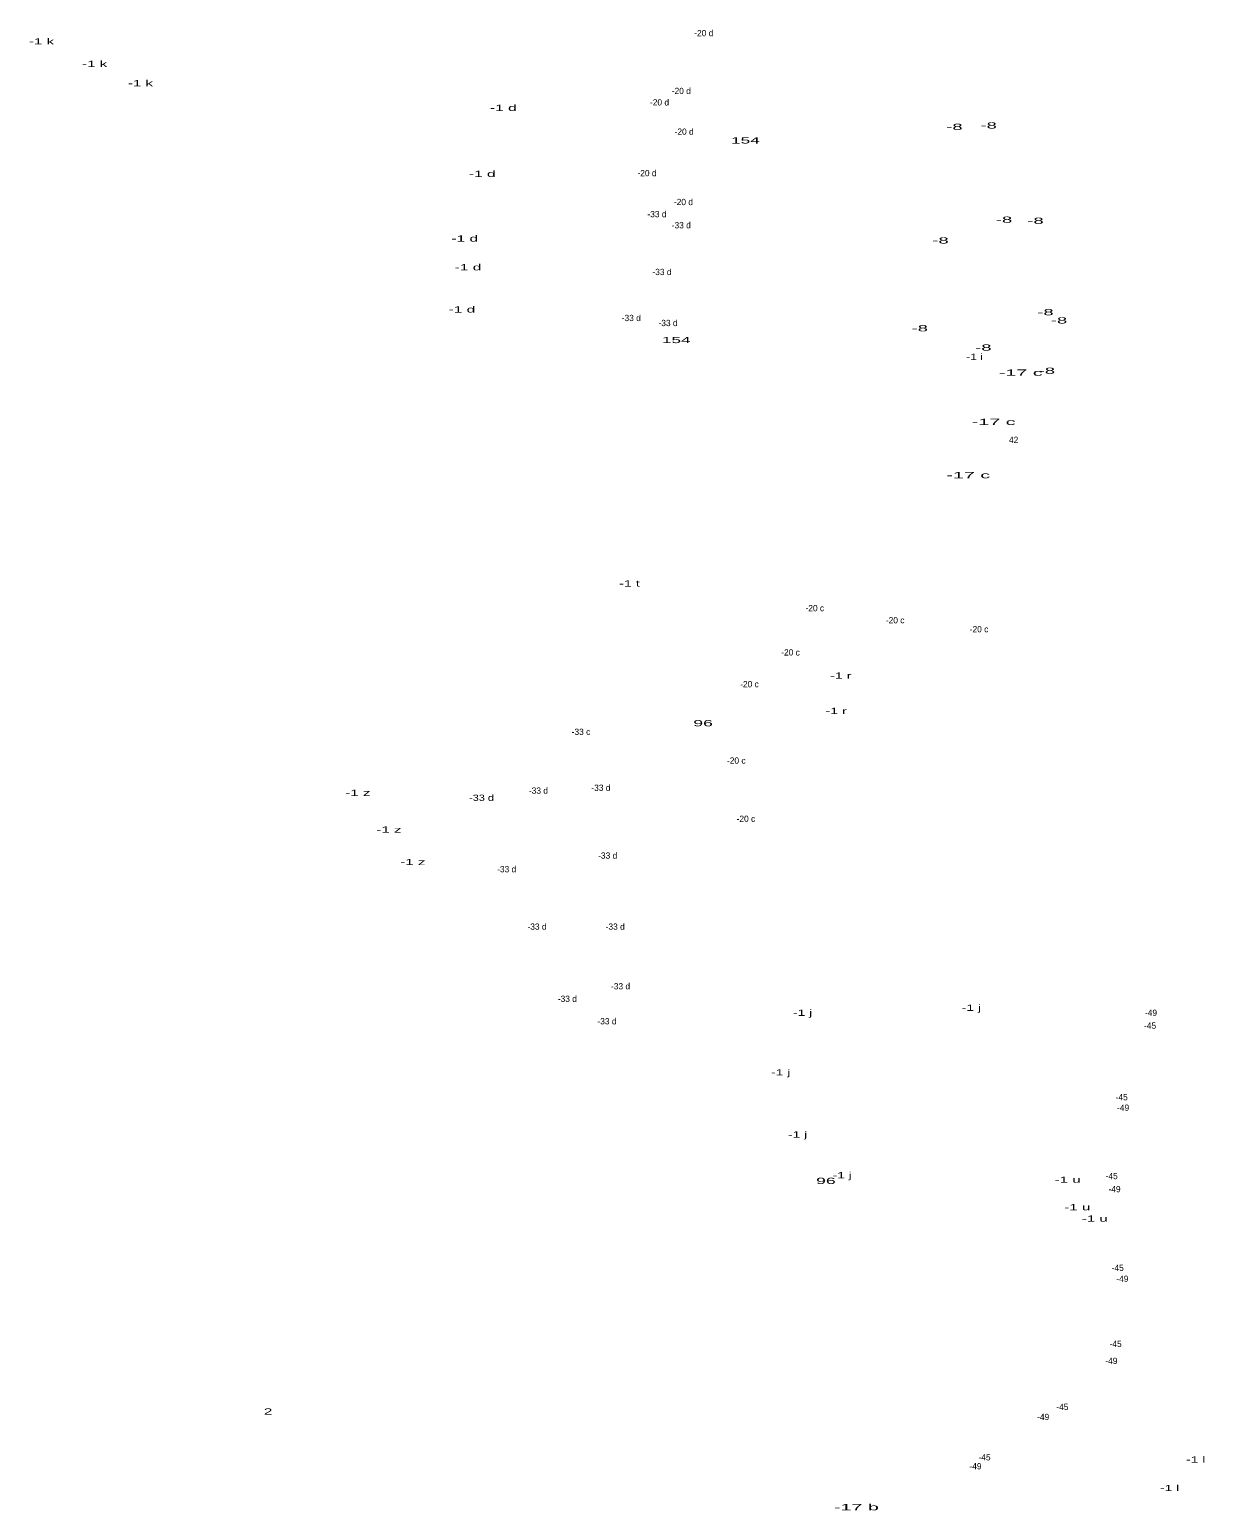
# Model space of a CAD drawing. Extents: x -668622 to -666786, y -990362 to -986505.
# Drawn here: x -667536 to -666786, y -988432 to -987486 of the extents above; entities that cross this region are included whole.
import ezdxf
from ezdxf.enums import TextEntityAlignment as Align

# ---------------------------------------------------------------- set-up
doc = ezdxf.new("R2010")
doc.units = 0
doc.header["$LTSCALE"] = 1.6
doc.layers.add('24', color=7, linetype='Continuous')

msp = doc.modelspace()

# ---------------------------------------------------------------- texts
at = {"layer": '24'}
for s, width, p in [('-1 k', 1.8, (-667528.436, -987495.94)), ('-1 k', 1.8, (-667494.466, -987510.31)), ('-1 k', 1.8, (-667465.286, -987522.62)), ('-1 d', 1.85, (-667233.561, -987538.35)), ('-8', 2.2, (-666945.534, -987550.53)), ('-8', 2.2, (-666923.654, -987549.62)), ('154', 2.05, (-667079.023, -987559.18)), ('-1 d', 1.85, (-667247.011, -987580.53)), ('-8', 2.2, (-666913.854, -987609.82)), ('-8', 2.2, (-666893.784, -987610.5)), ('-1 d', 1.85, (-667258.181, -987621.81)), ('-8', 2.2, (-666954.424, -987623.05)), ('-1 d', 1.85, (-667256.131, -987640.19)), ('-1 d', 1.85, (-667260.011, -987667.1)), ('-8', 2.2, (-666887.404, -987668.88)), ('-8', 2.2, (-666878.744, -987674.12)), ('154', 2.05, (-667123.143, -987686.64)), ('-8', 2.2, (-666967.654, -987679.14)), ('-1 i', 1.45, (-666932.701, -987697.38)), ('-8', 2.2, (-666927.074, -987691.45)), ('-8', 2.2, (-666886.494, -987706.28)), ('-17 c', 2.35, (-666903.179, -987707.48)), ('-17 c', 2.35, (-666920.499, -987738.95)), ('-17 c', 2.35, (-666936.689, -987772.92)), ('-1 t', 1.7, (-667153.009, -987842.11)), ('-1 r', 1.7, (-667018.109, -987900.94)), ('-1 r', 1.7, (-667021.069, -987923.51)), ('96', 2.1, (-667106.011, -987931.34)), ('-1 z', 1.8, (-667326.436, -987975.74)), ('-33 d', 1.3, (-667247.49, -987978.93)), ('-1 z', 1.8, (-667306.606, -987999.23)), ('-1 z', 1.8, (-667291.336, -988019.98)), ('-1 j', 1.65, (-666934.678, -988113.02)), ('-1 j', 1.65, (-667042.508, -988116.21)), ('-1 j', 1.65, (-667056.418, -988154.3)), ('-1 j', 1.65, (-667045.698, -988193.97)), ('96', 2.1, (-667027.611, -988223.59)), ('-1 j', 1.65, (-667017.208, -988219.97)), ('-1 u', 1.8, (-666873.216, -988222.81)), ('-1 u', 1.8, (-666867.056, -988240.37)), ('-1 u', 1.8, (-666855.886, -988247.66)), ('2', 1.8, (-667383.761, -988370.85)), ('-1 l', 1.65, (-666791.464, -988401.49)), ('-1 l', 1.65, (-666808.104, -988419.73)), ('-17 b', 2.35, (-667008.105, -988431.95))]:
    msp.add_text(s, height=4, dxfattribs=dict(at, width=width)).set_placement(p, align=Align.CENTER)
for s, p in [('-20 d', (-667105.56, -987490.66)), ('-20 d', (-667119.92, -987527.6)), ('-20 d', (-667133.83, -987534.9)), ('-20 d', (-667118.1, -987553.6)), ('-20 d', (-667141.81, -987580.05)), ('-20 d', (-667118.55, -987598.52)), ('-33 d', (-667135.453, -987606.27)), ('-33 d', (-667119.953, -987613.34)), ('-33 d', (-667132.263, -987643.21)), ('-33 d', (-667151.873, -987672.58)), ('-33 d', (-667128.383, -987675.78)), ('42', (-666907.711, -987750.43)), ('-20 c', (-667034.66, -987857.84)), ('-20 c', (-666983.37, -987865.59)), ('-20 c', (-666929.8, -987871.29)), ('-20 c', (-667050.17, -987886.12)), ('-20 c', (-667076.38, -987906.41)), ('-33 c', (-667183.982, -987936.83)), ('-20 c', (-667084.82, -987955.21)), ('-33 d', (-667211.133, -987974.37)), ('-33 d', (-667171.243, -987972.55)), ('-20 c', (-667078.66, -987992.38)), ('-33 d', (-667166.913, -988015.87)), ('-33 d', (-667231.423, -988024.54)), ('-33 d', (-667212.053, -988061.25)), ('-33 d', (-667162.123, -988061.25)), ('-33 d', (-667158.703, -988099.33)), ('-33 d', (-667192.673, -988107.31)), ('-33 d', (-667167.363, -988121.68)), ('-49', (-666820.015, -988116.22)), ('-45', (-666820.569, -988124.43)), ('-45', (-666838.749, -988170.13)), ('-49', (-666837.805, -988176.88)), ('-45', (-666845.129, -988220.53)), ('-49', (-666843.275, -988228.87)), ('-45', (-666841.259, -988279.13)), ('-49', (-666838.255, -988286.1)), ('-45', (-666842.619, -988327.7)), ('-49', (-666845.325, -988338.55)), ('-45', (-666876.589, -988367.95)), ('-49', (-666888.865, -988374.35)), ('-49', (-666932.065, -988405.82)), ('-45', (-666926.289, -988400.11))]:
    msp.add_text(s, height=4, dxfattribs=at).set_placement(p, align=Align.CENTER)

doc.saveas('drawing.dxf')
